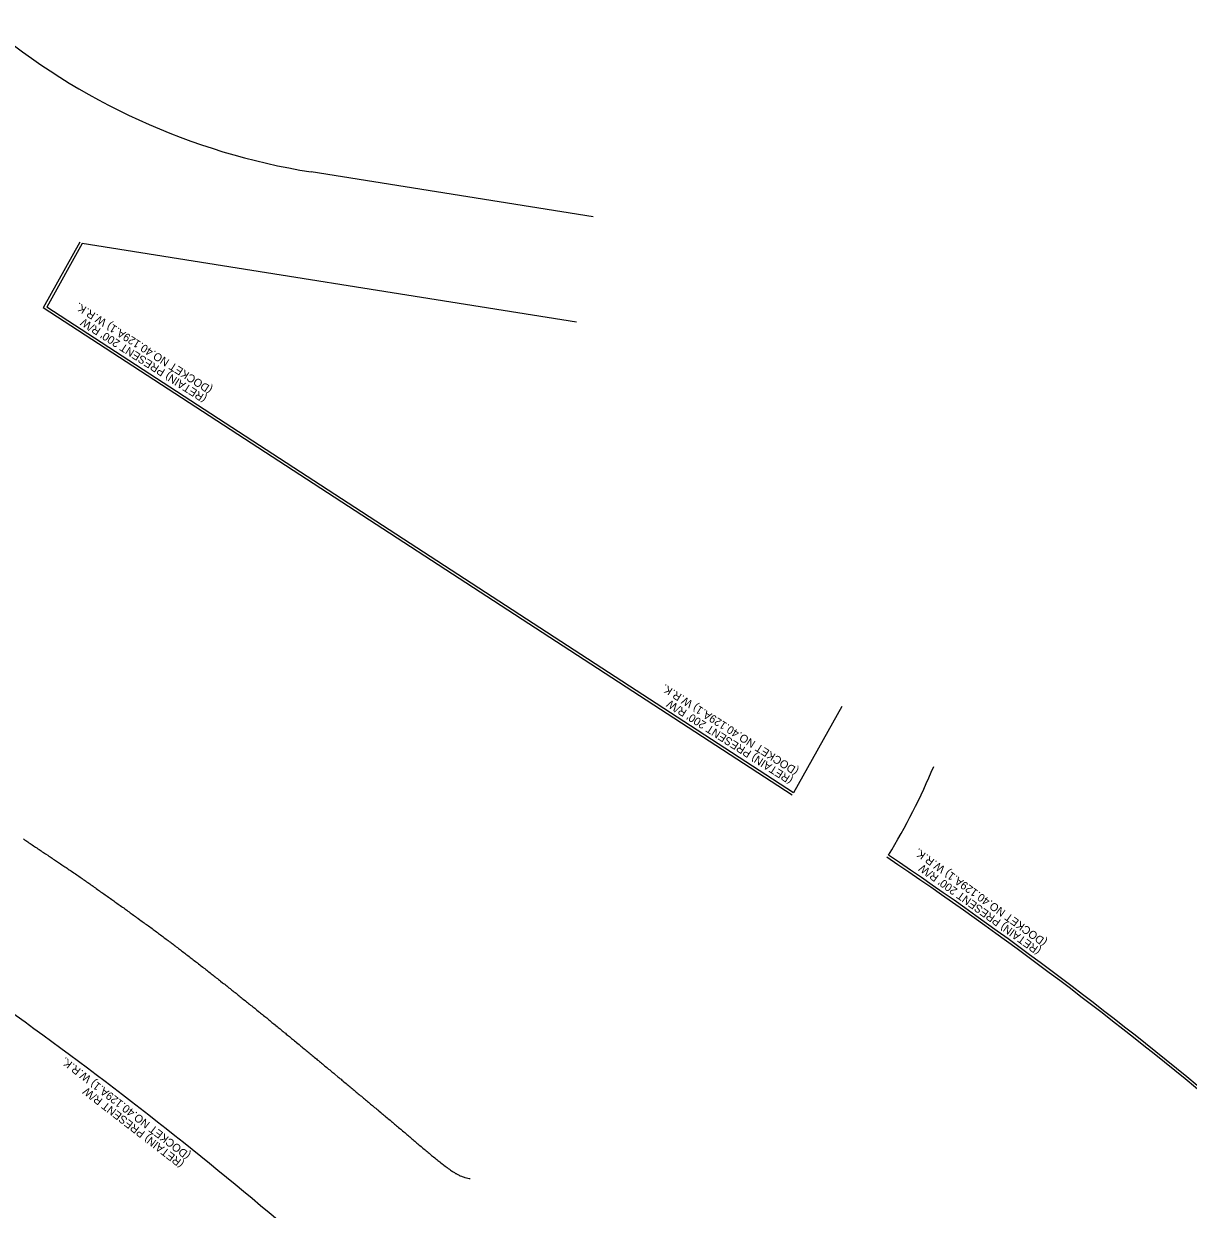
# Model space of a CAD drawing. Extents: x 2004008 to 2024436, y 806921 to 864820.
# Drawn here: x 2021860 to 2022733, y 814347 to 815236 of the extents above; entities that cross this region are included whole.
import ezdxf

# ---------------------------------------------------------------- set-up
doc = ezdxf.new("R2010")
doc.units = 0
for name, color, linetype in [('RD_PD_DR_ErosCtrl', 7, 'Continuous'), ('RD_PD_Final_LnLine', 7, 'Continuous'), ('RD_PD_MedBWall', 7, 'Continuous')]:
    doc.layers.add(name, color=color, linetype=linetype)

msp = doc.modelspace()

# ---------------------------------------------------------------- linework, layer by layer
at = {"layer": 'RD_PD_Final_LnLine'}
for p, q in [((2022287.05, 815090.99), (2022075.47, 815124.67)), ((2021904, 815070.96), (2021877.42, 815023.36)), ((2022274.48, 815011.99), (2021904, 815070.96)), ((2022437.28, 814659.24), (2021877.42, 815023.36)), ((2022473.54, 814723.94), (2022437.28, 814659.24))]:
    msp.add_line(p, q, dxfattribs=at)
for centre, radius, start, end in [((2022154.07, 815618.45), 500, 229.94631, 260.95528), ((2022110.82, 814857.63), 467.02, 328.36202, 337.53165), ((2020792.87, 812070.41), 3066.94, 50.0339, 55.98779), ((2020043.85, 811969.99), 3104.71, 47.90161, 57.69572)]:
    msp.add_arc(centre, radius, start, end, dxfattribs=at)
at = {"layer": 'RD_PD_MedBWall'}
for p in [(2021902.25, 815071.94), (2022436.19, 814657.56)]:
    msp.add_line(p, (2021874.76, 815022.7), dxfattribs=at)
msp.add_lwpolyline([(2021859.82, 814624.72), (2021860.65, 814624.17), (2021861.56, 814623.56), (2021862.39, 814623), (2021863.14, 814622.49), (2021863.97, 814621.94), (2021864.88, 814621.33), (2021865.63, 814620.82), (2021866.46, 814620.27), (2021867.37, 814619.66), (2021868.95, 814618.59), (2021869.78, 814618.04), (2021870.69, 814617.43), (2021871.52, 814616.87), (2021872.27, 814616.36), (2021873.1, 814615.81), (2021874.01, 814615.2), (2021874.84, 814614.64), (2021875.59, 814614.13), (2021876.42, 814613.58), (2021878.08, 814612.46), (2021878.91, 814611.91), (2021879.82, 814611.3), (2021880.65, 814610.74), (2021881.4, 814610.23), (2021882.23, 814609.68), (2021883.14, 814609.07), (2021883.97, 814608.51), (2021884.72, 814608), (2021885.5, 814607.48), (2021885.62, 814607.4), (2021886.06, 814607.11), (2021886.83, 814606.59), (2021887.65, 814606.05), (2021888.55, 814605.45), (2021889.29, 814604.95), (2021890.06, 814604.44), (2021890.97, 814603.84), (2021891.76, 814603.31), (2021892.58, 814602.77), (2021893.48, 814602.17), (2021894.22, 814601.67), (2021895.04, 814601.13), (2021895.94, 814600.53), (2021897.55, 814599.45), (2021897.95, 814599.18), (2021898.94, 814598.48), (2021899.81, 814597.88), (2021900.69, 814597.25), (2021901.39, 814596.75), (2021902.26, 814596.15), (2021903.14, 814595.52), (2021903.84, 814595.02), (2021904.66, 814594.45), (2021905.6, 814593.79), (2021906.34, 814593.26), (2021907.11, 814592.72), (2021908.05, 814592.06), (2021908.79, 814591.53), (2021909.56, 814590.99), (2021910.5, 814590.33), (2021911.31, 814589.75), (2021912.01, 814589.25), (2021912.88, 814588.65), (2021913.76, 814588.02), (2021914.46, 814587.52), (2021915.33, 814586.92), (2021916.21, 814586.29), (2021916.91, 814585.79), (2021917.73, 814585.22), (2021918.67, 814584.56), (2021919.41, 814584.03), (2021920.18, 814583.49), (2021921.12, 814582.83), (2021921.86, 814582.3), (2021922.63, 814581.76), (2021923.57, 814581.1), (2021924.31, 814580.57), (2021925.08, 814580.03), (2021926.02, 814579.37), (2021926.76, 814578.84), (2021927.53, 814578.3), (2021928.47, 814577.64), (2021929.21, 814577.11), (2021929.98, 814576.57), (2021930.87, 814575.94), (2021931.67, 814575.38), (2021932.48, 814574.81), (2021933.32, 814574.21), (2021934.21, 814573.58), (2021935.01, 814573.01), (2021935.86, 814572.38), (2021936.67, 814571.79), (2021937.42, 814571.25), (2021938.23, 814570.67), (2021939.1, 814570.03), (2021939.96, 814569.41), (2021940.7, 814568.87), (2021941.46, 814568.32), (2021942.33, 814567.68), (2021943.14, 814567.09), (2021943.89, 814566.55), (2021944.7, 814565.97), (2021945.57, 814565.33), (2021947.18, 814564.17), (2021947.98, 814563.59), (2021948.8, 814562.98), (2021949.55, 814562.44), (2021950.36, 814561.86), (2021951.23, 814561.22), (2021952.04, 814560.63), (2021952.79, 814560.09), (2021953.6, 814559.51), (2021954.52, 814558.84), (2021955.17, 814558.36), (2021955.28, 814558.28), (2021956.3, 814557.53), (2021957.15, 814556.9), (2021957.9, 814556.34), (2021958.71, 814555.75), (2021959.56, 814555.11), (2021960.31, 814554.56), (2021961.19, 814553.91), (2021961.97, 814553.32), (2021962.72, 814552.77), (2021963.53, 814552.17), (2021964.38, 814551.54), (2021965.13, 814550.98), (2021965.94, 814550.39), (2021966.79, 814549.75), (2021967.54, 814549.2), (2021968.35, 814548.6), (2021969.2, 814547.97), (2021970.12, 814547.28), (2021970.49, 814547), (2021971.28, 814546.39), (2021972.02, 814545.83), (2021972.88, 814545.17), (2021973.72, 814544.52), (2021974.46, 814543.95), (2021975.26, 814543.34), (2021976.1, 814542.69), (2021976.78, 814542.17), (2021977.58, 814541.57), (2021978.48, 814540.87), (2021979.22, 814540.3), (2021980.02, 814539.69), (2021980.81, 814539.08), (2021981.61, 814538.47), (2021982.39, 814537.87), (2021983.13, 814537.31), (2021983.99, 814536.65), (2021984.83, 814536), (2021985.57, 814535.43), (2021986.37, 814534.82), (2021987.15, 814534.22), (2021987.89, 814533.66), (2021988.75, 814533), (2021989.59, 814532.35), (2021990.33, 814531.78), (2021991.13, 814531.17), (2021992.06, 814530.45), (2021992.63, 814530), (2021993.45, 814529.37), (2021994.3, 814528.7), (2021994.97, 814528.17), (2021995.81, 814527.52), (2021996.66, 814526.85), (2021997.4, 814526.27), (2021998.17, 814525.66), (2021998.95, 814525.05), (2021999.76, 814524.42), (2022000.6, 814523.76), (2022001.31, 814523.19), (2022002.05, 814522.62), (2022002.96, 814521.91), (2022003.67, 814521.34), (2022004.46, 814520.73), (2022005.31, 814520.06), (2022006.05, 814519.48), (2022006.82, 814518.87), (2022007.6, 814518.26), (2022009.18, 814517.02), (2022009.96, 814516.41), (2022010.77, 814515.78), (2022011.61, 814515.12), (2022012.32, 814514.55), (2022013.06, 814513.98), (2022013.97, 814513.27), (2022014.76, 814512.64), (2022015.35, 814512.17), (2022016.16, 814511.52), (2022016.94, 814510.9), (2022017.72, 814510.27), (2022018.5, 814509.65), (2022019.23, 814509.06), (2022020.02, 814508.44), (2022020.85, 814507.77), (2022021.63, 814507.15), (2022022.41, 814506.52), (2022023.19, 814505.9), (2022023.97, 814505.27), (2022024.72, 814504.67), (2022026.28, 814503.42), (2022027.09, 814502.78), (2022027.87, 814502.15), (2022028.65, 814501.53), (2022029.43, 814500.9), (2022030.21, 814500.28), (2022030.99, 814499.65), (2022031.77, 814499.03), (2022032.5, 814498.44), (2022033.29, 814497.82), (2022034.12, 814497.15), (2022034.9, 814496.53), (2022035.87, 814495.75), (2022036.16, 814495.5), (2022036.81, 814494.98), (2022037.65, 814494.29), (2022038.42, 814493.65), (2022039.14, 814493.08), (2022039.96, 814492.4), (2022040.74, 814491.76), (2022041.52, 814491.12), (2022042.23, 814490.55), (2022043.07, 814489.86), (2022043.89, 814489.18), (2022044.55, 814488.65), (2022045.39, 814487.96), (2022046.21, 814487.28), (2022046.87, 814486.75), (2022047.71, 814486.06), (2022048.48, 814485.42), (2022049.2, 814484.85), (2022050.02, 814484.17), (2022050.8, 814483.53), (2022051.58, 814482.89), (2022052.29, 814482.32), (2022053.13, 814481.63), (2022053.95, 814480.95), (2022054.61, 814480.42), (2022055.45, 814479.73), (2022056.22, 814479.09), (2022056.94, 814478.52), (2022057.82, 814477.79), (2022058.54, 814477.19), (2022059.26, 814476.62), (2022060.03, 814475.99), (2022060.87, 814475.3), (2022061.69, 814474.62), (2022062.35, 814474.09), (2022063.19, 814473.4), (2022064.01, 814472.72), (2022064.7, 814472.16), (2022065.63, 814471.4), (2022066.47, 814470.7), (2022067.18, 814470.1), (2022067.95, 814469.46), (2022068.66, 814468.87), (2022069.43, 814468.24), (2022070.26, 814467.55), (2022071.03, 814466.91), (2022071.8, 814466.27), (2022072.51, 814465.68), (2022073.28, 814465.05), (2022074.11, 814464.36), (2022074.88, 814463.72), (2022075.65, 814463.08), (2022076.36, 814462.49), (2022077.13, 814461.86), (2022077.96, 814461.17), (2022078.73, 814460.53), (2022079.5, 814459.89), (2022080.21, 814459.3), (2022080.98, 814458.67), (2022081.81, 814457.98), (2022082.58, 814457.34), (2022083.35, 814456.7), (2022084.06, 814456.11), (2022084.83, 814455.48), (2022085.66, 814454.79), (2022086.43, 814454.15), (2022087.26, 814453.47), (2022087.95, 814452.88), (2022088.67, 814452.29), (2022089.5, 814451.6), (2022091.04, 814450.32), (2022091.75, 814449.73), (2022092.52, 814449.1), (2022093.35, 814448.41), (2022095.6, 814446.54), (2022096.37, 814445.91), (2022097.2, 814445.22), (2022097.96, 814444.59), (2022098.65, 814444.02), (2022099.43, 814443.37), (2022100.14, 814442.77), (2022101.74, 814441.45), (2022102.5, 814440.81), (2022103.21, 814440.21), (2022103.98, 814439.57), (2022104.75, 814438.93), (2022105.58, 814438.25), (2022106.34, 814437.61), (2022107.05, 814437.01), (2022107.82, 814436.37), (2022108.59, 814435.73), (2022109.42, 814435.05), (2022110.18, 814434.41), (2022110.89, 814433.81), (2022111.66, 814433.17), (2022112.43, 814432.53), (2022113.26, 814431.85), (2022114.08, 814431.16), (2022114.79, 814430.55), (2022115.5, 814429.96), (2022116.33, 814429.28), (2022117.09, 814428.64), (2022117.8, 814428.04), (2022118.57, 814427.4), (2022120.17, 814426.08), (2022120.93, 814425.44), (2022121.64, 814424.84), (2022122.41, 814424.2), (2022123.18, 814423.56), (2022124.01, 814422.88), (2022124.77, 814422.24), (2022125.48, 814421.64), (2022126.25, 814421), (2022127.85, 814419.68), (2022128.61, 814419.04), (2022129.32, 814418.44), (2022130.09, 814417.8), (2022130.86, 814417.16), (2022131.69, 814416.48), (2022132.45, 814415.84), (2022133.16, 814415.24), (2022133.93, 814414.6), (2022134.76, 814413.92), (2022135.75, 814413.08), (2022135.87, 814412.97), (2022136.52, 814412.44), (2022138.09, 814411.09), (2022138.85, 814410.45), (2022139.62, 814409.79), (2022140.33, 814409.2), (2022141.14, 814408.51), (2022141.96, 814407.81), (2022142.72, 814407.16), (2022143.37, 814406.61), (2022144.14, 814405.97), (2022145.01, 814405.22), (2022145.71, 814404.62), (2022146.47, 814403.98), (2022147.29, 814403.28), (2022148, 814402.67), (2022148.71, 814402.08), (2022149.52, 814401.39), (2022151.04, 814400.09), (2022151.75, 814399.5), (2022152.58, 814398.79), (2022153.33, 814398.15), (2022154.09, 814397.51), (2022154.91, 814396.81), (2022155.62, 814396.2), (2022156.33, 814395.61), (2022157.14, 814394.92), (2022157.96, 814394.22), (2022158.66, 814393.62), (2022159.37, 814393.03), (2022160.2, 814392.32), (2022161.01, 814391.63), (2022161.71, 814391.03), (2022162.47, 814390.39), (2022163.24, 814389.73), (2022163.95, 814389.14), (2022164.47, 814388.69), (2022165.13, 814388.17), (2022165.91, 814387.54), (2022166.58, 814387.01), (2022167.37, 814386.39), (2022168.2, 814385.73), (2022168.99, 814385.1), (2022169.78, 814384.47), (2022170.55, 814383.86), (2022171.33, 814383.24), (2022172.06, 814382.66), (2022172.91, 814381.99), (2022173.74, 814381.32), (2022174.46, 814380.75), (2022174.94, 814380.37), (2022176.07, 814379.53), (2022176.87, 814378.93), (2022177.62, 814378.38), (2022178.43, 814377.78), (2022179.28, 814377.15), (2022180.03, 814376.59), (2022180.84, 814376), (2022181.01, 814375.87), (2022181.36, 814375.66), (2022182.16, 814375.17), (2022183.02, 814374.64), (2022183.92, 814374.09), (2022184.24, 814373.89), (2022184.63, 814373.68), (2022185.52, 814373.21), (2022186.44, 814372.71), (2022186.64, 814372.61), (2022187.42, 814372.25), (2022188.25, 814371.88), (2022188.79, 814371.63), (2022189.54, 814371.4), (2022190.37, 814371.16), (2022190.7, 814371.06), (2022191.12, 814370.97), (2022192.08, 814370.76), (2022193.08, 814370.54), (2022194.05, 814370.33), (2022194.13, 814370.31), (2022194.67, 814370.24), (2022194.71, 814370.24)], dxfattribs=at)
msp.add_arc((2020792.87, 812070.41), 3064.94, 50.0339, 55.98779, dxfattribs=at)

# ---------------------------------------------------------------- texts
at = {"layer": 'RD_PD_DR_ErosCtrl'}
for s, rotation, p in [('(DOCKET NO.40.129A.1) W.R.K.', 147.52288, (2022002.09, 814962.94)), ("(RETAIN) PRESENT 200' R/W", 147.52288, (2021997.84, 814956.26)), ('(DOCKET NO.40.129A.1) W.R.K.', 147.52288, (2022441.61, 814677.02)), ("(RETAIN) PRESENT 200' R/W", 147.52288, (2022437.36, 814670.35)), ('(DOCKET NO.40.129A.1) W.R.K.', 144.3547, (2022627.91, 814548.55)), ("(RETAIN) PRESENT 200' R/W", 144.3547, (2022623.3, 814542.12)), ('(DOCKET NO.40.129A.1) W.R.K.', 142.31389, (2021985.6, 814388.59)), ('(RETAIN) PRESENT R/W', 142.31389, (2021980.77, 814382.33))]:
    msp.add_text(s, height=6, rotation=rotation, dxfattribs=at).set_placement(p)

doc.saveas('drawing.dxf')
